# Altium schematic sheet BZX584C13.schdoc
size 127 x 101 mm
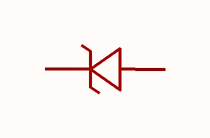
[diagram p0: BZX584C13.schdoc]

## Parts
U?  bzx584c13  [SOD-523_L1.2-W0.8-LS1.6-RD]  (value not drawn)

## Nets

Not connected (* = marked no-connect by the designer): U? 1(K) 2(A)

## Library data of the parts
U? = bzx584c13: 二极管配置:1个独立式;稳压值(标称值):13V;稳压值(范围值):12.4V~14.1V;耗散功率(Pd):150mW;; Manufacturer: CJ(江苏长电/长晶); AddInBom: yes; ModelId: 8f56a03db567494d8f4c9d12aa52a741; ModelName: SOD-523_L1.2-W0.8-H0.7-LS1.6; ModelTransform: 62.992,31.496,0,180,0,0,0,0,0; Diode Configuration: 1个独立式; Zener Voltage(Nom): 13V; Reverse Leakage Current (Ir): 100nA; Pd - Power Dissipation: 150mW; Impedance(Zzt): 30Ω; Impedance(Zzk): 170Ω; Operating Junction Temperature Range: -55℃~+150℃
